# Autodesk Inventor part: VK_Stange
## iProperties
Created: 2004-01
Part Number: VK_Stange
Material: Stahl (schweißbar)
Document SubType Name: Modellieren
Designer: Ulrich
Control State: 0
Master: False
Checked Out: False
Shininess: 20.0
Angle Display Precision: 2
Document Length Units: 11269
Document Angle Units: 11279
Document Time Units: 11290
Document Mass Units: 11283
Document Length Units Precision: 3
Document Angle Units Precision: 2
Density: 0.0
Volumn: 0.0
Area: 0.0
PropertySet Name: Model Information
Author: Ulrich
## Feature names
1. Grundkörper [Revolution]
2. Bolzenbohrung [Extrusion]
